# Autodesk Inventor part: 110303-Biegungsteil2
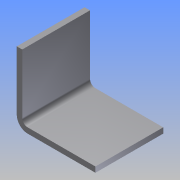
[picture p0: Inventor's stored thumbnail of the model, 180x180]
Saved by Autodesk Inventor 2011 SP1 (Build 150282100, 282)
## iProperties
Manager: Michael Puschner
Company: Mensch und Maschine Scholle GmbH
Created: 2011-03
Part Number: 110303-Biegungsteil2
Document SubType Name: Blech
Designer: MP
Mass: 20.6283 g
Surface Area: 115.393 cm^2
Volume: 20.6283 cm^3
Density: 1 g/cm^3
Flat Pattern Width: 5 cm
Flat Pattern Length: 10 cm
Flat Pattern Area: 50 cm^2
Sheet Metal Rule: Standard
Sheet Metal Width: 50,000 mm
Sheet Metal Length: 100,000 mm
Sheet Metal Area: 5000,000 mm^2
Title: Norm.ipt
Author: MP
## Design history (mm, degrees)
sketch "Skizze1"
  geometry: L1 (-50, 25)-(50, 25); L2 (50, 25)-(50, -25); L3 (50, -25)-(-50, -25); L4 (-50, -25)-(-50, 25); L5 (0, 25)-(0, -25); 2 further points
  constraints: 10 end point, 3 midpoint, 2 parallel, 1 horizontal, 1 horizontal alignment, 1 perpendicular, 1 vertical alignment
  dimensions: "d0" = 100 distance of L1.start L1.end; "d1" = 50 distance of L3.end L1.start
extrude "Extrusion1" new body sketch "Skizze1" distance "d2" = 4; taper "d3" = 0 deg
feature "Biegungsteil1" dims "d4" = 4, "d5" = 90 deg
node "Volumenkörper1"
feature "Definition1"
other parameters: "Stärke" = 4 (derived), "KFaktor" = 4.4, "Biegeradius" = 4 (= Stärke), "BreiteBiegungsfreistellung" = 4 (= Stärke), "TiefeBiegungsfreistellung" = 2 (= 0.5 x Stärke), "GrößeEckenfreistellung" = 16 (= 4 x Stärke), "AbstandVerbindung" = 0.01, "MinimalRest" = 8 (= 2 x Stärke), "Übergangsradius" = 4 (= Biegeradius), "JacobiRadiusGröße" = 4 (= Biegeradius), "Abstandsgröße" = 4 (= Stärke), "Abstandsgröße" = 4, "Biegeradius" = 4, "BreiteBiegungsfreistellung" = 4, "GrößeEckenfreistellung" = 16, "JacobiRadiusGröße" = 4, "MinimalRest" = 8, "Stärke" = 4, "TiefeBiegungsfreistellung" = 2, "Übergangsradius" = 4
